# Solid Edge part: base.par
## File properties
Author: there
Template: iso metric part.par
Last saved by: there
Revision: 17
Application: Solid Edge
Precisión: 0.990
Username: there
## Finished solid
Body 1: solid body, 34 faces, 92 edges, 56 vertices.
  Faces by surface: plane 30, cylinder 4
  Edges by curve: line 84, circle 8
Bounding box of the edges (mm): 240.000 x 3.000 x 100.000, from (-135, -3, -50) to (105, 0, 50).
Cylindrical faces by radius (mm): R2.5 x2, R3.2 x2
Planar faces by outward normal: +x 5, +y 1, +z 7, -x 9, -y 1, -z 7
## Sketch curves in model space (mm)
line (105, -3, 50) -> (105, -3, 30)
line (105, -3, -50) -> (105, -3, -30)
line (-65, -3, 0) -> (-110, -3, 0)
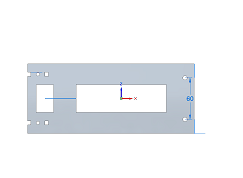
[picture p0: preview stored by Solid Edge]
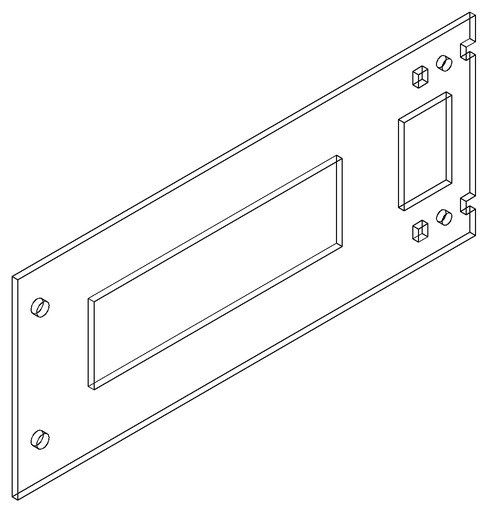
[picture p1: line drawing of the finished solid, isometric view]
